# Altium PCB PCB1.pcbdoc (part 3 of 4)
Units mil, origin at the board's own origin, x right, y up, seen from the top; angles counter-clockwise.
Board outline 6180 x 7065 mil, 2 copper layers (Top Layer, Bottom Layer); 471 components, 245 nets, 1464 pads, 505 vias.
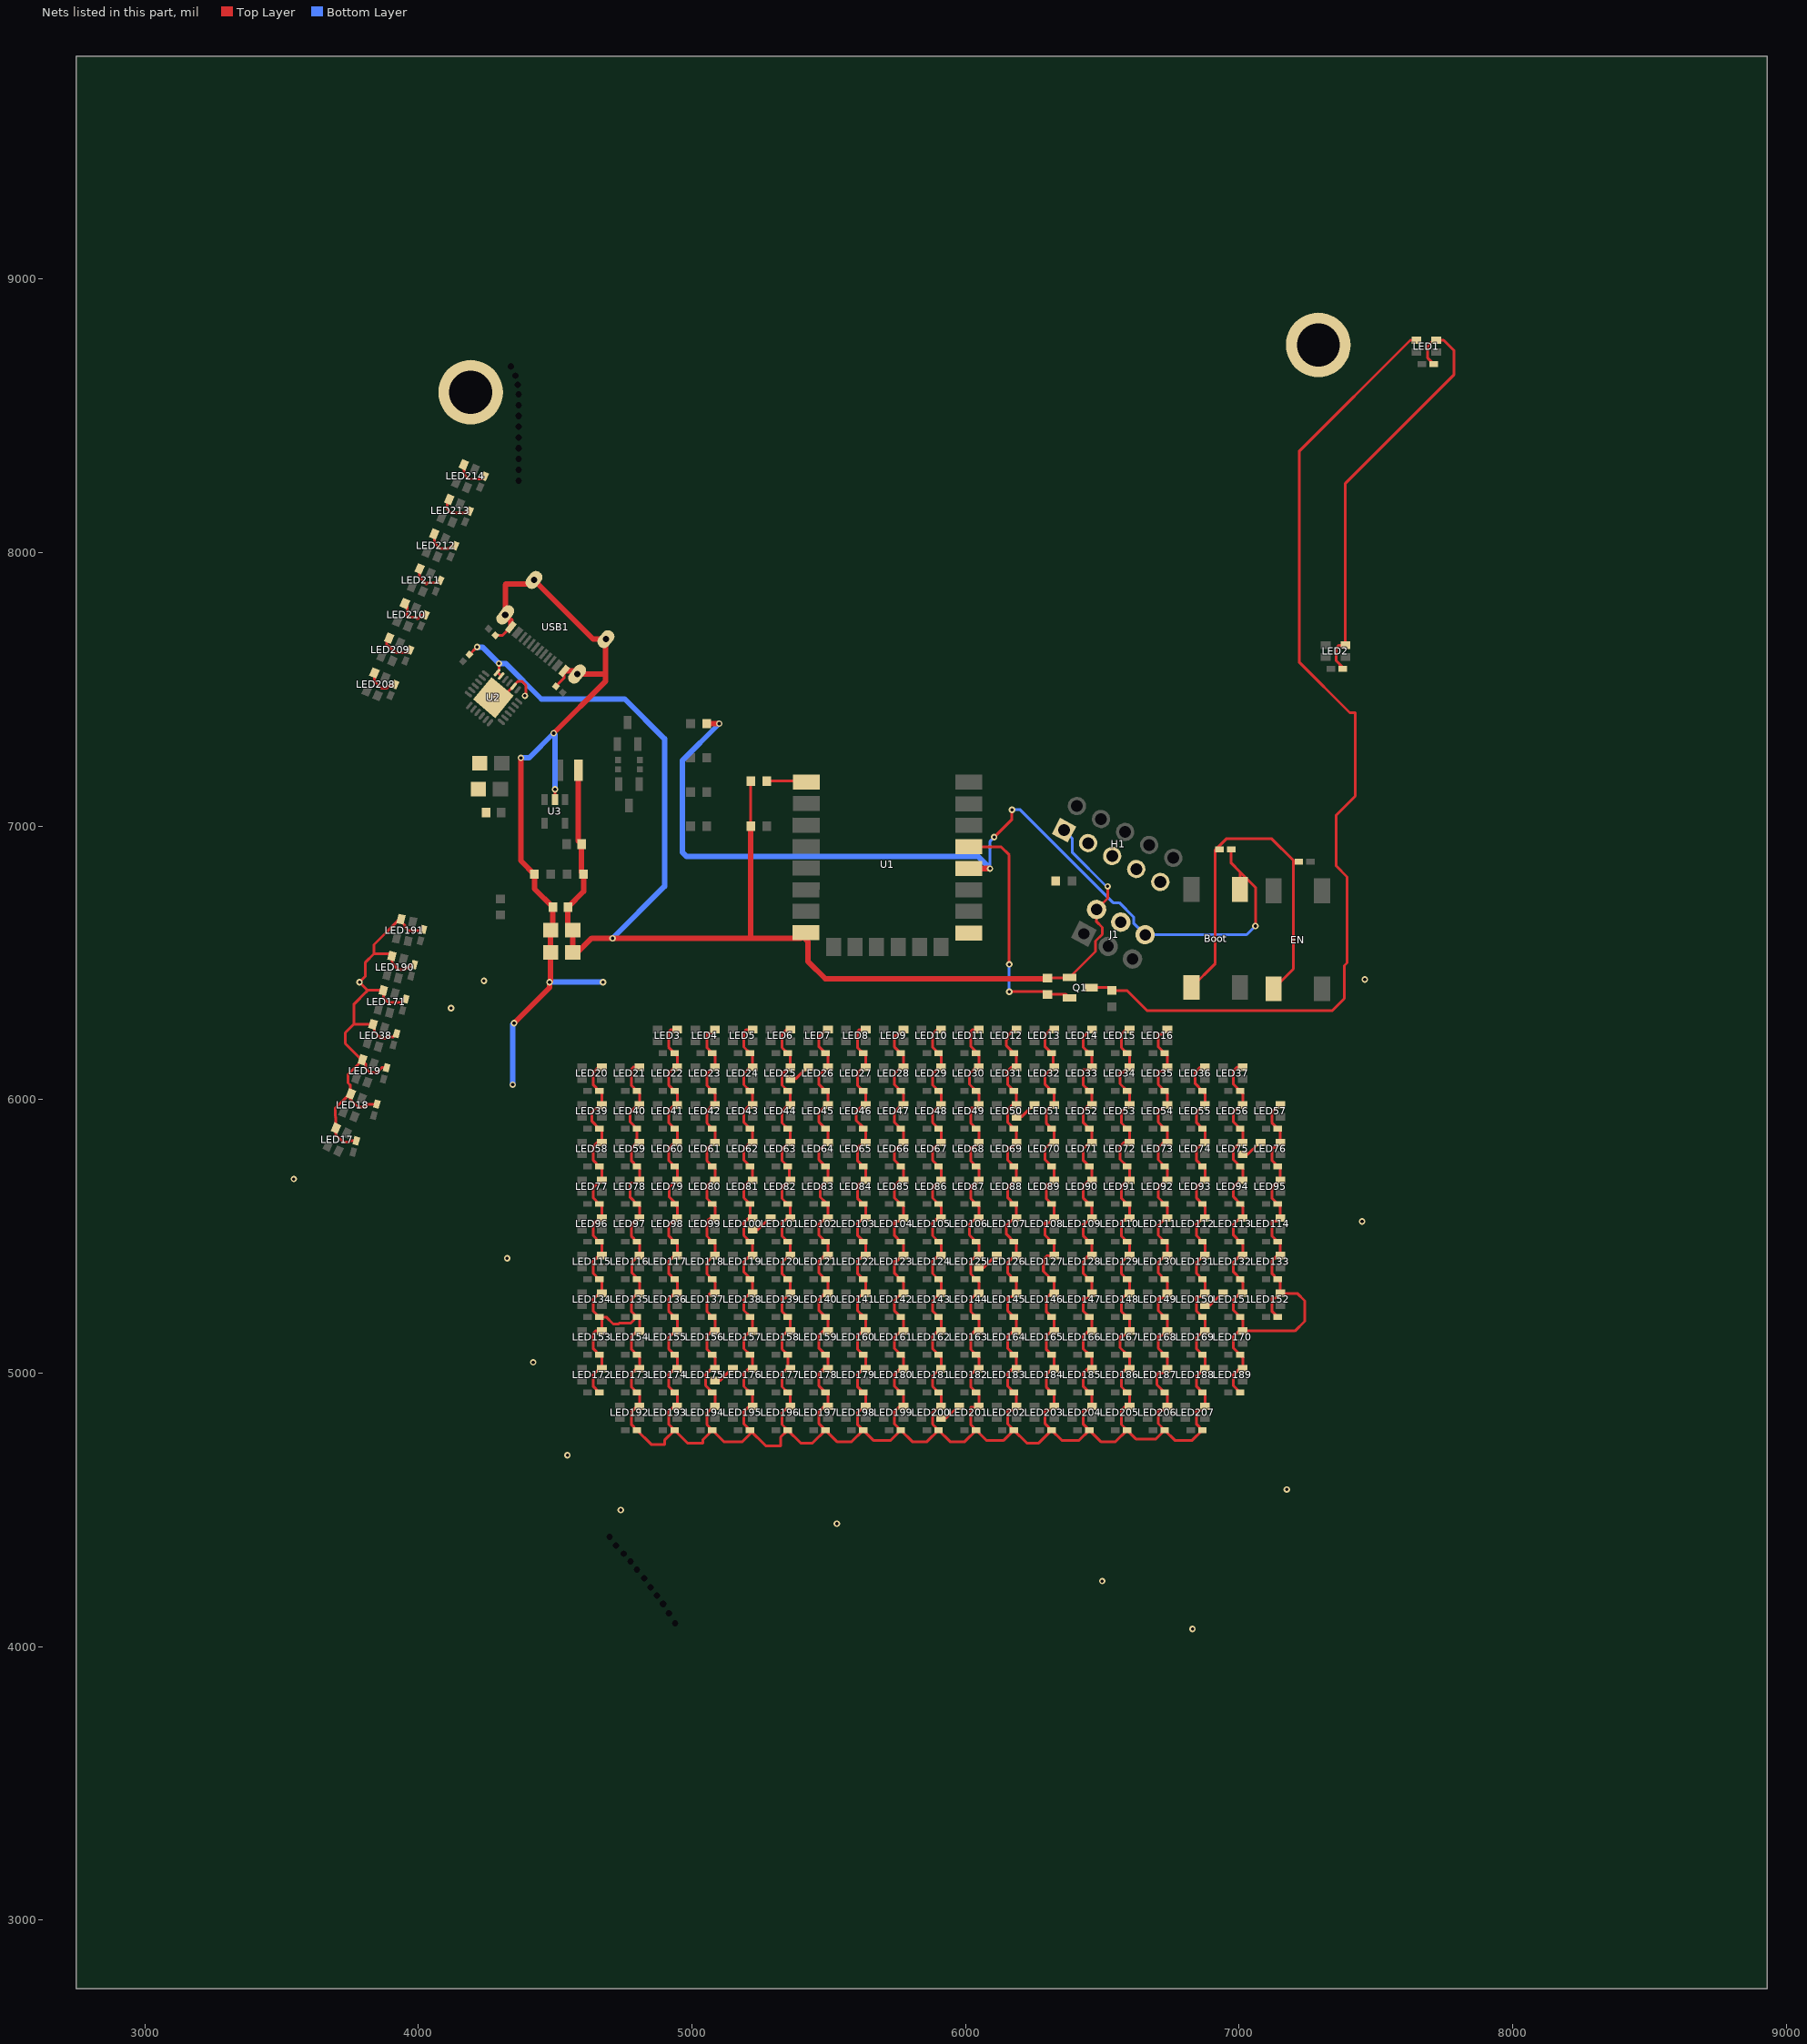
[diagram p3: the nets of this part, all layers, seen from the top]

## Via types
v1: diameter 24.02, hole 12.01, Top Layer to Bottom Layer, 504 vias
v2: diameter 23.62, hole 12.01, Top Layer to Bottom Layer, 1 vias

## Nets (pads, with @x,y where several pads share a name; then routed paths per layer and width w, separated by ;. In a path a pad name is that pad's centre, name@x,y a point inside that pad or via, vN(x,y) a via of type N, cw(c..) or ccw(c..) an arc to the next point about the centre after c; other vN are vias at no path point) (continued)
GND: Boot.1 C1.1 C2.1 C3.1 C4.1 C5.1 C6.1 C7.1 C8.1 C9.1 C10.1 C11.1 C12.1 C13.1 C14.1 C15.1 C16.1 C17.1 C18.1 C19.1 C20.1 C21.1 C22.1 C23.1 C24.1 C25.1 C26.1 C27.1 C28.1 C29.1 C30.1 C31.1 C32.1 C33.1 C34.1 C35.1 C36.1 C37.1 C38.1 C39.1 C40.1 C41.1 C42.1 C43.1 C44.1 C45.1 C46.1 C47.1 C48.1 C49.1 C50.1 C51.1 C52.1 C53.1 C54.1 C55.1 C56.1 C57.1 C58.1 C59.1 C60.1 C61.1 C62.1 C63.1 C64.1 C65.1 C66.1 C67.1 C68.1 C69.1 C70.1 C71.1 C72.1 C73.1 C74.1 C75.1 C76.1 C77.1 C78.1 C79.1 C80.1 C81.1 C82.1 C83.1 C84.1 C85.1 C86.1 C87.1 C88.1 C89.1 C90.1 C91.1 C92.1 C93.1 C94.1 C95.1 C96.1 C97.1 C98.1 C99.1 C100.1 C101.1 C102.1 C103.1 C104.1 C105.1 C106.1 C107.1 C108.1 C109.1 C110.1 C111.1 C112.1 C113.1 C114.1 C115.1 C116.1 C117.1 C118.1 C119.1 C120.1 C121.1 C122.1 C123.1 C124.1 C125.1 C126.1 C127.1 C128.1 C129.1 C130.1 C131.1 C132.1 C133.1 C134.1 C135.1 C136.1 C137.1 C138.1 C139.1 C140.1 C141.1 C142.1 C143.1 C144.1 C145.1 C146.1 C147.1 C148.1 C149.1 C150.1 C151.1 C152.1 C153.1 C154.1 C155.1 C156.1 C157.1 C158.1 C159.1 C160.1 C161.1 C162.1 C163.1 C164.1 C165.1 C166.1 C167.1 C168.1 C169.1 C170.1 C171.1 C172.1 C173.1 C174.1 C175.1 C176.1 C177.1 C178.1 C179.1 C180.1 C181.1 C182.1 C183.1 C184.1 C185.1 C186.1 C187.1 C188.1 C189.1 C190.1 C191.1 C192.1 C193.1 C194.1 C195.1 C196.1 C197.1 C198.1 C199.1 C200.1 C201.1 C202.1 C203.1 C204.1 C205.1 C206.1 C207.1 C208.1 C209.1 C210.1 C211.1 C212.1 C213.1 C214.1 C226.2 C227.2 C229.1 C230.1 C231.1 C233.1 C234.1 C235.1 EN.1 H1.3 H1.5 H1.7 H1.9 J1.4 LED1.2 LED2.2 LED3.2 LED4.2 LED5.2 LED6.2 LED7.2 LED8.2 LED9.2 LED10.2 LED11.2 LED12.2 LED13.2 LED14.2 LED15.2 LED16.2 LED17.2 LED18.2 LED19.2 LED20.2 LED21.2 LED22.2 LED23.2 LED24.2 LED25.2 LED26.2 LED27.2 LED28.2 LED29.2 LED30.2 LED31.2 LED32.2 LED33.2 LED34.2 LED35.2 LED36.2 LED37.2 LED38.2 LED39.2 LED40.2 LED41.2 LED42.2 LED43.2 LED44.2 LED45.2 LED46.2 LED47.2 LED48.2 LED49.2 LED50.2 LED51.2 LED52.2 LED53.2 LED54.2 LED55.2 LED56.2 LED57.2 LED58.2 LED59.2 LED60.2 LED61.2 LED62.2 LED63.2 LED64.2 LED65.2 LED66.2 LED67.2 LED68.2 LED69.2 LED70.2 LED71.2 LED72.2 LED73.2 LED74.2 LED75.2 LED76.2 LED77.2 LED78.2 LED79.2 LED80.2 LED81.2 LED82.2 LED83.2 LED84.2 LED85.2 LED86.2 LED87.2 LED88.2 LED89.2 LED90.2 LED91.2 LED92.2 LED93.2 LED94.2 LED95.2 LED96.2 LED97.2 LED98.2 LED99.2 LED100.2 LED101.2 LED102.2 LED103.2 LED104.2 LED105.2 LED106.2 LED107.2 LED108.2 LED109.2 LED110.2 LED111.2 LED112.2 LED113.2 LED114.2 LED115.2 LED116.2 LED117.2 LED118.2 LED119.2 LED120.2 LED121.2 LED122.2 LED123.2 LED124.2 LED125.2 LED126.2 LED127.2 LED128.2 LED129.2 LED130.2 LED131.2 LED132.2 LED133.2 LED134.2 LED135.2 LED136.2 LED137.2 LED138.2 LED139.2 LED140.2 LED141.2 LED142.2 LED143.2 LED144.2 LED145.2 LED146.2 LED147.2 LED148.2 LED149.2 LED150.2 LED151.2 LED152.2 LED153.2 LED154.2 LED155.2 LED156.2 LED157.2 LED158.2 LED159.2 LED160.2 LED161.2 LED162.2 LED163.2 LED164.2 LED165.2 LED166.2 LED167.2 LED168.2 LED169.2 LED170.2 LED171.2 LED172.2 LED173.2 LED174.2 LED175.2 LED176.2 LED177.2 LED178.2 LED179.2 LED180.2 LED181.2 LED182.2 LED183.2 LED184.2 LED185.2 LED186.2 LED187.2 LED188.2 LED189.2 LED190.2 LED191.2 LED192.2 LED193.2 LED194.2 LED195.2 LED196.2 LED197.2 LED198.2 LED199.2 LED200.2 LED201.2 LED202.2 LED203.2 LED204.2 LED205.2 LED206.2 LED207.2 LED208.2 LED209.2 LED210.2 LED211.2 LED212.2 LED213.2 LED214.2 pad.26 R3.1 R7.1 R8.1 R16.1 U1.9 U2.2 U2.25 U3.2 USB1.1 USB1.12 USB1.13 USB1.14 | length 45240
  Top Layer w10: LED18.2@3750.11,6016.53 3750.11,6002.83 3779.99,5972.95 3804.28,5972.95 3813.94,5982.61 C18.1@3846.22,5982.61 ; LED18.2@3755.23,6023.8 LED18.2@3751.93,6023.8 ; C17.1@3774.07,5849.89 3752.76,5849.89 3748.2,5845.33 3725.52,5845.33 3698.16,5872.7 3698.16,5937.08 3695.99,5939.24 3695.99,5967.86 LED18.2@3751.93,6023.8 ; LED19.2@3797.49,6146.83 LED19.2@3794.67,6144 ; 3810.95,6393.15 3810.95,6395.31 ; LED38.2@3834.37,6275.78 3764.11,6275.78 ; LED38.2@3839.28,6273.52 3839.28,6247.84 3862.13,6225 3880,6225 3885,6230 3908.65,6230 C38.1@3920.51,6241.86 ; LED208.2@3839.71,7560.42 3839.71,7530.29 3865,7505 3885,7505 3895,7515 3913.01,7515 C208.1@3915.71,7517.7 ; LED171.2@3872.5,6399.21 3872.5,6373.53 3891.03,6355 3935,6355 3947.55,6367.55 C171.1@3953.73,6367.55 ; LED171.2@3875.56,6400.96 3816.61,6400.96 3810.95,6395.31 ; C19.1@3885.26,6117.22 3866.54,6117.22 3849.03,6099.7 3822.92,6099.7 3807.46,6115.17 3807.46,6131.21 LED19.2@3794.67,6144 ; LED209.2@3893.65,7687.22 3885,7678.57 3885,7660 3890,7660 3915,7635 3960.15,7635 C209.1@3969.64,7644.5 ; LED190.2@3901.41,6527.49 3895.48,6533.41 3837.87,6533.41 ; LED190.2@3904.01,6525.35 3904.01,6499.67 3928.68,6475 3950,6475 3955,6480 3960,6480 3973.69,6493.69 C190.1@3985.24,6493.69 ; LED191.2@3930.21,6658.32 3950.94,6637.6 3950.94,6631.42 3963.8,6618.56 4016.98,6618.56 C191.1@4018.78,6620.37 ; LED191.2@3933.44,6662.63 3837.87,6567.06 3837.87,6533.41 ; LED210.2@3950.89,7814.66 3960,7805.56 3960,7765 3990,7765 3995,7760 4000,7760 4006.51,7766.51 4006.51,7771.51 4006.94,7771.94 C210.1@4026.89,7771.94 ; LED211.2@4004.83,7941.46 4004.83,7910.17 4030,7885 4035,7890 4072.09,7890 C211.1@4080.83,7898.74 ; LED212.2@4058.77,8068.26 4058.77,8036.23 4080,8015 4110,8015 4120.54,8025.54 C212.1@4134.76,8025.54 ; LED213.2@4112.7,8195.06 4105,8187.36 4105,8160 4120,8145 4181.36,8145 C213.1@4188.7,8152.34 ; LED214.2@4166.64,8321.86 4166.64,8288.36 4185,8270 4233.49,8270 C214.1@4242.64,8279.14 ; U2.25@4281.89,7468.8 4305.53,7468.8 U2.2@4347.16,7510.43 ; R8.1@4282.35,7698.26 4308.7,7698.26 USB1.12@4338.3,7727.87 ; U2.2@4354.15,7519.47 4365.18,7530.51 4378.26,7530.51 4393.56,7515.2 4393.56,7480.57 v2(4389.85,7476.85) ; U3.2@4499.29,7097.6 4500,7098.31 v1(4500,7135) ; R7.1@4502.47,7511.54 4532.85,7541.93 USB1.1@4532.85,7567.74 ; C172.1@4661.46,4929.84 4640,4951.3 4640,4995.47 4661.02,5016.5 LED172.2@4671.02,5016.5 4671.02,5058.07 C153.1@4661.46,5067.64 4640,5089.1 4640,5145.98 4648.31,5154.29 LED153.2@4671.02,5154.29 4671.02,5195.87 C134.1@4661.46,5205.43 ; LED20.2@4671.02,6118.86 4658.86,6118.86 4640,6100 4640,6053.66 C20.1@4661.46,6032.2 4671.02,6022.64 LED39.2@4671.02,5981.06 4659.63,5969.67 4649.67,5969.67 4635,5955 4635,5920.87 C39.1@4661.46,5894.41 4671.02,5884.84 LED58.2@4671.02,5843.27 4653.27,5843.27 4640,5830 4640,5778.07 C58.1@4661.46,5756.61 4671.02,5747.05 LED77.2@4671.02,5705.47 4665.47,5705.47 4640,5680 4640,5640.28 C77.1@4661.46,5618.82 4671.02,5609.25 LED96.2@4671.02,5567.68 4661.02,5567.68 4640,5546.65 4640,5502.48 C96.1@4661.46,5481.02 4671.02,5471.46 LED115.2@4671.02,5429.88 4659.88,5429.88 4640,5410 4640,5364.69 C115.1@4661.46,5343.23 4671.02,5333.66 LED134.2@4671.02,5292.09 4661.02,5292.09 4640,5271.06 4640,5226.89 C134.1@4661.46,5205.43 ; LED21.2@4808.82,6118.86 4786.1,6118.86 4780,6112.76 4780,6051.46 C21.1@4799.26,6032.2 4808.82,6022.64 LED40.2@4808.82,5981.06 4801.06,5981.06 4775,5955 4775,5918.66 C40.1@4799.26,5894.41 4799.26,5852.83 LED59.2@4808.82,5843.27 4798.27,5843.27 4780,5825 4780,5775.87 C59.1@4799.26,5756.61 4808.82,5747.05 LED78.2@4808.82,5705.47 4798.35,5695 4775,5695 4775,5643.07 C78.1@4799.26,5618.82 4808.82,5609.25 LED97.2@4808.82,5567.68 4802.68,5567.68 4780,5545 4780,5500.28 C97.1@4799.26,5481.02 4808.82,5471.46 LED116.2@4808.82,5429.88 4805.1,5429.88 4780.12,5404.9 4780.12,5368.24 4799.26,5349.11 C116.1@4799.26,5343.23 4808.82,5333.66 LED135.2@4808.82,5292.09 4802.09,5292.09 4780,5270 4780,5224.69 C135.1@4799.26,5205.43 ; LED3.2@4946.62,6256.65 4923.9,6256.65 4915,6247.76 4915,6192.05 C3.1@4937.05,6170 4946.62,6160.44 LED22.2@4946.62,6118.86 4936.62,6118.86 4915,6097.24 4915,6054.26 C22.1@4937.05,6032.2 4946.62,6022.64 LED41.2@4946.62,5981.06 4936.62,5981.06 4915,5959.45 4915,5916.46 C41.1@4937.05,5894.41 4946.62,5884.84 LED60.2@4946.62,5843.27 4936.62,5843.27 4915,5821.65 4915,5778.66 C60.1@4937.05,5756.61 4946.62,5747.05 LED79.2@4946.62,5705.47 4942.9,5705.47 4917.91,5680.49 4917.91,5643.83 4937.05,5624.7 C79.1@4937.05,5618.82 4946.62,5609.25 LED98.2@4946.62,5567.68 4942.68,5567.68 4915,5540 4915,5503.07 C98.1@4937.05,5481.02 4946.62,5471.46 LED117.2@4946.62,5429.88 4936.62,5429.88 4915,5408.27 4915,5365.28 C117.1@4937.05,5343.23 4946.62,5333.66 LED136.2@4946.62,5292.09 4936.62,5292.09 4915,5270.47 4915,5227.48 C136.1@4937.05,5205.43 4946.62,5195.87 LED155.2@4946.62,5154.29 4939.29,5154.29 4915,5130 4915,5089.69 C155.1@4937.05,5067.64 4946.62,5058.07 LED174.2@4946.62,5016.5 4936.62,5016.5 4915,4994.88 4915,4951.89 C174.1@4937.05,4929.84 4946.62,4920.28 LED193.2@4946.62,4878.7 4933.7,4878.7 4915,4860 4915,4814.1 C193.1@4937.05,4792.05 ; LED4.2@5084.41,6256.65 5072.76,6245 5055,6245 5056.72,6243.28 5056.72,6231.72 5055,6230 5055,6189.85 C4.1@5074.85,6170 5084.41,6160.44 LED23.2@5084.41,6118.86 5080.47,6118.86 5061.61,6100 5055,6100 5055,6052.05 C23.1@5074.85,6032.2 5084.41,6022.64 LED42.2@5084.41,5981.06 5076.06,5981.06 5055,5960 5055,5914.26 C42.1@5074.85,5894.41 5084.41,5884.84 LED61.2@5084.41,5843.27 5078.27,5843.27 5055,5820 5055,5776.46 C61.1@5074.85,5756.61 5084.41,5747.05 LED80.2@5084.41,5705.47 5075.47,5705.47 5055,5685 5055,5638.66 C80.1@5074.85,5618.82 5084.41,5609.25 LED99.2@5084.41,5567.68 5067.68,5567.68 5058.11,5558.11 5058.11,5545 5055,5545 5055,5500.87 C99.1@5074.85,5481.02 5084.41,5471.46 LED118.2@5084.41,5429.88 5079.88,5429.88 5055,5405 5055,5363.07 C118.1@5074.85,5343.23 5084.41,5333.66 LED137.2@5084.41,5292.09 5067.09,5292.09 5055,5280 5056.41,5278.59 5056.41,5266.41 5055,5265 5055,5225.28 C137.1@5074.85,5205.43 5084.41,5195.87 LED156.2@5084.41,5154.29 5074.29,5154.29 5055,5135 5055,5087.48 C156.1@5074.85,5067.64 5084.41,5058.07 LED175.2@5084.41,5016.5 5071.5,5016.5 5050,4995 5050,4954.69 C175.1@5074.85,4929.84 5084.41,4920.28 LED194.2@5084.41,4878.7 5078.7,4878.7 5055,4855 5055,4811.89 C194.1@5074.85,4792.05 ; LED5.2@5222.21,6256.65 5199.49,6256.65 5190,6247.17 5190,6192.64 C5.1@5212.64,6170 5222.21,6160.44 LED24.2@5222.21,6118.86 5212.21,6118.86 5190,6096.65 5190,6054.85 C24.1@5212.64,6032.2 5222.21,6022.64 LED43.2@5222.21,5981.06 5212.21,5981.06 5190,5958.86 5190,5917.05 C43.1@5212.64,5894.41 5222.21,5884.84 LED62.2@5222.21,5843.27 5212.21,5843.27 5190,5821.06 5190,5779.26 C62.1@5212.64,5756.61 5222.21,5747.05 LED81.2@5222.21,5705.47 5212.21,5705.47 5190,5683.27 5190,5641.46 C81.1@5212.64,5618.82 5212.64,5577.24 LED100.2@5222.21,5567.68 5207.42,5567.68 5190,5550.26 5190,5503.66 C100.1@5212.64,5481.02 5222.21,5471.46 LED119.2@5222.21,5429.88 5212.21,5429.88 5190,5407.68 5190,5370 5212.64,5347.36 C119.1@5212.64,5343.23 5222.21,5333.66 LED138.2@5222.21,5292.09 5212.21,5292.09 5190,5269.88 5190,5230 5212.64,5207.36 C138.1@5212.64,5205.43 5222.21,5195.87 LED157.2@5222.21,5154.29 5214.29,5154.29 5190,5130 5190,5090.28 C157.1@5212.64,5067.64 5222.21,5058.07 LED176.2@5222.21,5016.5 5206.5,5016.5 5190,5000 5190,4952.48 C176.1@5212.64,4929.84 5222.21,4920.28 LED195.2@5222.21,4878.7 5208.7,4878.7 5190,4860 5190,4814.69 C195.1@5212.64,4792.05 ; LED82.2@5360,5705.47 LED82.2@5356.06,5705.47 ; LED6.2@5360,6256.65 5346.65,6256.65 5330,6240 5330,6190.44 C6.1@5350.44,6170 5360,6160.44 LED25.2@5360,6118.86 5356.06,6118.86 5337.2,6100 5330,6100 5330,6052.64 C25.1@5350.44,6032.2 5360,6022.64 LED44.2@5360,5981.06 5351.06,5981.06 5330,5960 5330,5914.85 C44.1@5350.44,5894.41 5360,5884.84 LED63.2@5360,5843.27 5353.27,5843.27 5330,5820 5330,5777.05 C63.1@5350.44,5756.61 5356.06,5750.99 LED82.2@5356.06,5705.47 ; LED7.2@5497.8,6256.65 5491.65,6256.65 5465,6230 5465,6193.23 C7.1@5488.23,6170 5497.8,6160.44 LED26.2@5497.8,6118.86 5493.86,6118.86 5465,6090 5465,6055.44 C26.1@5488.23,6032.2 5497.8,6022.64 LED45.2@5497.8,5981.06 5491.06,5981.06 5465,5955 5465,5917.64 C45.1@5488.23,5894.41 5497.8,5884.84 LED64.2@5497.8,5843.27 5493.27,5843.27 5465,5815 5465,5779.85 C64.1@5488.23,5756.61 5497.8,5747.05 LED83.2@5497.8,5705.47 5494.08,5705.47 5469.1,5680.49 5469.1,5643.83 5488.23,5624.7 C83.1@5488.23,5618.82 5497.8,5609.25 LED102.2@5497.8,5567.68 5487.68,5567.68 5465,5545 5465,5504.26 C102.1@5488.23,5481.02 5497.8,5471.46 LED121.2@5497.8,5429.88 5484.88,5429.88 5465,5410 5465,5366.46 C121.1@5488.23,5343.23 5497.8,5333.66 LED140.2@5497.8,5292.09 5487.09,5292.09 5465,5270 5465,5228.66 C140.1@5488.23,5205.43 5497.8,5195.87 LED159.2@5497.8,5154.29 5479.29,5154.29 5465,5140 5465,5090.87 C159.1@5488.23,5067.64 5497.8,5058.07 LED178.2@5497.8,5016.5 5481.5,5016.5 5465,5000 5465,4953.07 C178.1@5488.23,4929.84 5497.8,4920.28 LED197.2@5497.8,4878.7 5483.7,4878.7 5465,4860 5465,4815.28 C197.1@5488.23,4792.05 ; LED8.2@5635.59,6256.65 5612.88,6256.65 5605,6248.78 5605,6191.03 C8.1@5626.03,6170 5635.59,6160.44 LED27.2@5635.59,6118.86 5625.59,6118.86 5605,6098.27 5605,6053.23 C27.1@5626.03,6032.2 5635.59,6022.64 LED46.2@5635.59,5981.06 5625.59,5981.06 5600,5955.47 5600,5925 5626.03,5898.97 C46.1@5626.03,5894.41 5635.59,5884.84 LED65.2@5635.59,5843.27 5625.59,5843.27 5605,5822.68 5605,5777.64 C65.1@5626.03,5756.61 5635.59,5747.05 LED84.2@5635.59,5705.47 5625.59,5705.47 5605,5684.88 5605,5639.85 C84.1@5626.03,5618.82 5635.59,5609.25 LED103.2@5635.59,5567.68 5625.59,5567.68 5605,5547.09 5605,5505 5626.03,5483.97 C103.1@5626.03,5481.02 5635.59,5471.46 LED122.2@5635.59,5429.88 5625.59,5429.88 5605,5409.29 5605,5365 5626.03,5343.97 C122.1@5626.03,5343.23 5635.59,5333.66 LED141.2@5635.59,5292.09 5625.59,5292.09 5605,5271.5 5605,5230 5626.03,5208.97 C141.1@5626.03,5205.43 5635.59,5195.87 LED160.2@5635.59,5154.29 5624.29,5154.29 5605,5135 5605,5088.66 C160.1@5626.03,5067.64 5635.59,5058.07 LED179.2@5635.59,5016.5 5626.5,5016.5 5605,4995 5605,4950.87 C179.1@5626.03,4929.84 5635.59,4920.28 LED198.2@5635.59,4878.7 5628.7,4878.7 5605,4855 5605,4813.07 C198.1@5626.03,4792.05 ; LED9.2@5773.39,6256.65 5769.45,6256.65 5747.8,6235 5740,6235 5740,6193.82 C9.1@5763.82,6170 5773.39,6160.44 LED28.2@5773.39,6118.86 5763.86,6118.86 5740,6095 5740,6056.03 C28.1@5763.82,6032.2 5773.39,6022.64 LED47.2@5773.39,5981.06 5766.06,5981.06 5740,5955 5740,5918.23 C47.1@5763.82,5894.41 5773.39,5884.84 LED66.2@5773.39,5843.27 5768.27,5843.27 5740,5815 5740,5780.44 C66.1@5763.82,5756.61 5773.39,5747.05 LED85.2@5773.39,5705.47 5760.47,5705.47 5740,5685 5740,5642.64 C85.1@5763.82,5618.82 5773.39,5609.25 LED104.2@5773.39,5567.68 5760.71,5555 5740,5555 5740,5504.85 C104.1@5763.82,5481.02 5773.39,5471.46 LED123.2@5773.39,5429.88 5769.45,5429.88 5749.57,5410 5740,5410 5740,5367.05 C123.1@5763.82,5343.23 5773.39,5333.66 LED142.2@5773.39,5292.09 5767.09,5292.09 5740,5265 5740,5229.26 C142.1@5763.82,5205.43 5773.39,5195.87 LED161.2@5773.39,5154.29 5764.29,5154.29 5740,5130 5740,5091.46 C161.1@5763.82,5067.64 5773.39,5058.07 LED180.2@5773.39,5016.5 5761.5,5016.5 5740,4995 5740,4953.66 C180.1@5763.82,4929.84 5773.39,4920.28 LED199.2@5773.39,4878.7 5758.7,4878.7 5740,4860 5740,4815.87 C199.1@5763.82,4792.05 ; 5884.16,4855 5880,4855 ; LED10.2@5911.18,6256.65 5896.65,6256.65 5880,6240 5880,6191.62 C10.1@5901.62,6170 5911.18,6160.44 LED29.2@5911.18,6118.86 5903.86,6118.86 5880,6095 5880,6053.82 C29.1@5901.62,6032.2 5911.18,6022.64 LED48.2@5911.18,5981.06 5906.06,5981.06 5880,5955 5880,5916.03 C48.1@5901.62,5894.41 5911.18,5884.84 LED67.2@5911.18,5843.27 5903.27,5843.27 5880,5820 5880,5778.23 C67.1@5901.62,5756.61 5911.18,5747.05 LED86.2@5911.18,5705.47 5905.47,5705.47 5880,5680 5880,5640.44 C86.1@5901.62,5618.82 5911.18,5609.25 LED105.2@5911.18,5567.68 5897.68,5567.68 5880,5550 5880,5502.64 C105.1@5901.62,5481.02 5911.18,5471.46 LED124.2@5911.18,5429.88 5899.88,5429.88 5880,5410 5880,5364.85 C124.1@5901.62,5343.23 5911.18,5333.66 LED143.2@5911.18,5292.09 5907.09,5292.09 5880,5265 5880,5227.05 C143.1@5901.62,5205.43 5911.18,5195.87 LED162.2@5911.18,5154.29 5899.29,5154.29 5880,5135 5880,5089.26 C162.1@5901.62,5067.64 5911.18,5058.07 LED181.2@5911.18,5016.5 5906.5,5016.5 5880,4990 5880,4951.46 C181.1@5901.62,4929.84 5911.18,4920.28 LED200.2@5911.18,4878.7 5903.7,4878.7 5880,4855 ; LED11.2@6048.98,6256.65 6026.26,6256.65 6020,6250.39 6020,6195 6039.41,6175.59 C11.1@6039.41,6170 6048.98,6160.44 LED30.2@6048.98,6118.86 6038.98,6118.86 6015,6094.88 6015,6056.62 C30.1@6039.41,6032.2 6048.98,6022.64 LED49.2@6048.98,5981.06 6037.91,5970 6020,5970 6021.43,5968.57 6021.43,5956.43 6020,5955 6020,5913.82 C49.1@6039.41,5894.41 6048.98,5884.84 LED68.2@6048.98,5843.27 6030.71,5825 6020,5825 6020,5776.03 C68.1@6039.41,5756.61 6048.98,5747.05 LED87.2@6048.98,5705.47 6045.04,5705.47 6024.57,5685 6020,5685 6020,5638.23 C87.1@6039.41,5618.82 6048.98,5609.25 LED106.2@6048.98,5567.68 6037.68,5567.68 6015,5545 6015,5505.44 C106.1@6039.41,5481.02 6048.98,5471.46 LED125.2@6048.98,5429.88 6039.88,5429.88 6020,5410 6020,5362.64 C125.1@6039.41,5343.23 6048.98,5333.66 LED144.2@6048.98,5292.09 6042.09,5292.09 6020,5270 6020,5224.85 C144.1@6039.41,5205.43 6048.98,5195.87 LED163.2@6048.98,5154.29 6034.29,5154.29 6020,5140 6020,5087.05 C163.1@6039.41,5067.64 6048.98,5058.07 LED182.2@6048.98,5016.5 6041.5,5016.5 6020,4995 6020,4949.26 C182.1@6039.41,4929.84 6048.98,4920.28 LED201.2@6048.98,4878.7 6045.28,4875 6020,4875 6020,4811.46 C201.1@6039.41,4792.05 ; LED12.2@6186.77,6256.65 6176.65,6256.65 6155,6235 6155,6225 6150,6220 6150,6197.21 C12.1@6177.21,6170 6186.77,6160.44 LED31.2@6186.77,6118.86 6168.86,6118.86 6150,6100 6155,6095 6155,6054.41 C31.1@6177.21,6032.2 6186.77,6022.64 LED50.2@6186.77,5981.06 6171.06,5981.06 6155,5965 6155,5916.62 C50.1@6177.21,5894.41 6186.77,5884.84 LED69.2@6186.77,5843.27 6168.5,5825 6155,5825 6155,5778.82 C69.1@6177.21,5756.61 6186.77,5747.05 LED88.2@6186.77,5705.47 6180.47,5705.47 6155,5680 6155,5641.03 C88.1@6177.21,5618.82 6186.77,5609.25 LED107.2@6186.77,5567.68 6177.68,5567.68 6150,5540 6150,5508.23 C107.1@6177.21,5481.02 6186.77,5471.46 LED126.2@6186.77,5429.88 6179.88,5429.88 6155,5405 6155,5365.44 C126.1@6177.21,5343.23 6186.77,5333.66 LED145.2@6186.77,5292.09 6174.68,5280 6155,5280 6155,5227.64 C145.1@6177.21,5205.43 6186.77,5195.87 LED164.2@6186.77,5154.29 6174.29,5154.29 6155,5135 6155,5089.85 C164.1@6177.21,5067.64 6186.77,5058.07 LED183.2@6186.77,5016.5 6171.5,5016.5 6155,5000 6155,4952.05 C183.1@6177.21,4929.84 6186.77,4920.28 LED202.2@6186.77,4878.7 6173.07,4865 6155,4865 6155,4814.26 C202.1@6177.21,4792.05 ; LED32.2@6324.57,6118.86 LED32.2@6320.63,6118.86 ; LED13.2@6324.57,6256.65 6311.65,6256.65 6290,6235 6290,6195 C13.1@6315,6170 6320.63,6164.37 LED32.2@6320.63,6118.86 ; LED14.2@6462.36,6256.65 6458.43,6256.65 6436.77,6235 6430,6235 6430,6192.8 C14.1@6452.8,6170 6462.36,6160.44 LED33.2@6462.36,6118.86 6453.5,6110 6430,6110 6430,6055 C33.1@6452.8,6032.2 6462.36,6022.64 LED52.2@6462.36,5981.06 6451.06,5981.06 6430,5960 6430,5917.21 C52.1@6452.8,5894.41 6462.36,5884.84 LED71.2@6462.36,5843.27 6453.27,5843.27 6430,5820 6430,5779.41 C71.1@6452.8,5756.61 6462.36,5747.05 LED90.2@6462.36,5705.47 6450.47,5705.47 6430,5685 6430,5641.62 C90.1@6452.8,5618.82 6462.36,5609.25 LED109.2@6462.36,5567.68 6458.43,5567.68 6435.75,5545 6430,5545 6430,5503.82 C109.1@6452.8,5481.02 6462.36,5471.46 LED128.2@6462.36,5429.88 6449.88,5429.88 6435,5415 6435,5410 6430,5405 6430,5366.03 C128.1@6452.8,5343.23 6462.36,5333.66 LED147.2@6462.36,5292.09 6445.28,5275 6430,5275 6430,5228.23 C147.1@6452.8,5205.43 6462.36,5195.87 LED166.2@6462.36,5154.29 6449.29,5154.29 6430,5135 6430,5090.44 C166.1@6452.8,5067.64 6462.36,5058.07 LED185.2@6462.36,5016.5 6446.5,5016.5 6430,5000 6430,4952.64 C185.1@6452.8,4929.84 6462.36,4920.28 LED204.2@6462.36,4878.7 6448.66,4865 6430,4865 6430,4814.85 C204.1@6452.8,4792.05 ; LED15.2@6600.16,6256.65 6586.65,6256.65 6570,6240 6570,6190.59 C15.1@6590.59,6170 6600.16,6160.44 LED34.2@6600.16,6118.86 6596.22,6118.86 6577.36,6100 6565,6100 6565,6057.8 C34.1@6590.59,6032.2 6600.16,6022.64 LED53.2@6600.16,5981.06 6596.22,5981.06 6575.16,5960 6570,5960 6570,5915 C53.1@6590.59,5894.41 6600.16,5884.84 LED72.2@6600.16,5843.27 6578.27,5843.27 6565,5830 6565,5782.21 C72.1@6590.59,5756.61 6600.16,5747.05 LED91.2@6600.16,5705.47 6590.47,5705.47 6570,5685 6570,5639.41 C91.1@6590.59,5618.82 6600.16,5609.25 LED110.2@6600.16,5567.68 6587.68,5567.68 6570,5550 6570,5501.62 C110.1@6590.59,5481.02 6600.16,5471.46 LED129.2@6600.16,5429.88 6594.88,5429.88 6570,5405 6570,5363.82 C129.1@6590.59,5343.23 6600.16,5333.66 LED148.2@6600.16,5292.09 6592.09,5292.09 6570,5270 6570,5226.03 C148.1@6590.59,5205.43 6600.16,5195.87 LED167.2@6600.16,5154.29 6596.22,5154.29 6576.93,5135 6565,5135 6565,5093.23 C167.1@6590.59,5067.64 6600.16,5058.07 LED186.2@6600.16,5016.5 6586.5,5016.5 6570,5000 6570,4950.44 C186.1@6590.59,4929.84 6600.16,4920.28 LED205.2@6600.16,4878.7 6583.7,4878.7 6570,4865 6570,4812.64 C205.1@6590.59,4792.05 ; LED16.2@6737.95,6256.65 6721.3,6240 6705,6240 6705,6193.39 C16.1@6728.39,6170 6737.95,6160.44 LED35.2@6737.95,6118.86 6724.09,6105 6705,6105 6705,6055.59 C35.1@6728.39,6032.2 6737.95,6022.64 LED54.2@6737.95,5981.06 6721.89,5965 6705,5965 6705,5917.8 C54.1@6728.39,5894.41 6737.95,5884.84 LED73.2@6737.95,5843.27 6723.27,5843.27 6705,5825 6705,5780 C73.1@6728.39,5756.61 6737.95,5747.05 LED92.2@6737.95,5705.47 6730.47,5705.47 6705,5680 6705,5642.21 C92.1@6728.39,5618.82 6737.95,5609.25 LED111.2@6737.95,5567.68 6732.68,5567.68 6705,5540 6705,5504.41 C111.1@6728.39,5481.02 6737.95,5471.46 LED130.2@6737.95,5429.88 6729.88,5429.88 6705,5405 6705,5366.62 C130.1@6728.39,5343.23 6737.95,5333.66 LED149.2@6737.95,5292.09 6720.87,5275 6705,5275 6705,5228.82 C149.1@6728.39,5205.43 6737.95,5195.87 LED168.2@6737.95,5154.29 6734.02,5154.29 6714.72,5135 6705,5135 6705,5091.03 C168.1@6728.39,5067.64 6737.95,5058.07 LED187.2@6737.95,5016.5 6721.46,5000 6700,5000 6700,4958.23 C187.1@6728.39,4929.84 6737.95,4920.28 LED206.2@6737.95,4878.7 6724.25,4865 6705,4865 6705,4815.44 C206.1@6728.39,4792.05 ; Boot.1@6826.41,6410.87 6913.54,6497.99 6913.54,6913.54 6955,6955 7118.54,6955 7198.54,6875 7198.54,6477.99 EN.1@7126.41,6405.87 ; LED36.2@6875.75,6118.86 6858.86,6118.86 6840,6100 6840,6058.39 C36.1@6866.18,6032.2 6875.75,6022.64 LED55.2@6875.75,5981.06 6871.06,5981.06 6845,5955 6845,5915.59 C55.1@6866.18,5894.41 6875.75,5884.84 LED74.2@6875.75,5843.27 6868.27,5843.27 6845,5820 6845,5777.8 C74.1@6866.18,5756.61 6875.75,5747.05 LED93.2@6875.75,5705.47 6870.47,5705.47 6845,5680 6845,5640 C93.1@6866.18,5618.82 6875.75,5609.25 LED112.2@6875.75,5567.68 6867.68,5567.68 6845,5545 6845,5502.21 C112.1@6866.18,5481.02 6875.75,5471.46 LED131.2@6875.75,5429.88 6869.88,5429.88 6845,5405 6845,5364.41 C131.1@6866.18,5343.23 6875.75,5333.66 LED150.2@6875.75,5292.09 6863.66,5280 6845,5280 6845,5226.62 C150.1@6866.18,5205.43 6875.75,5195.87 LED169.2@6875.75,5154.29 6869.29,5154.29 6845,5130 6845,5088.82 C169.1@6866.18,5067.64 6875.75,5058.07 LED188.2@6875.75,5016.5 6871.5,5016.5 6845,4990 6845,4951.03 C188.1@6866.18,4929.84 6875.75,4920.28 LED207.2@6875.75,4878.7 6862.05,4865 6845,4865 6845,4813.23 C207.1@6866.18,4792.05 6829.14,4755 6765.44,4755 C206.1@6728.39,4792.05 ; C189.1@7003.98,4929.84 6980,4953.82 6980,4995 7001.5,5016.5 LED189.2@7013.54,5016.5 7013.54,5058.07 C170.1@7003.98,5067.64 6980,5091.62 6980,5135 6999.29,5154.29 LED170.2@7013.54,5154.29 ; LED37.2@7013.54,6118.86 6993.86,6118.86 6980,6105 6980,6056.18 C37.1@7003.98,6032.2 7013.54,6022.64 LED56.2@7013.54,5981.06 7006.06,5981.06 6980,5955 6980,5918.39 C56.1@7003.98,5894.41 7013.54,5884.84 LED75.2@7013.54,5843.27 7003.54,5843.27 6980,5819.72 6980,5780.59 C75.1@7003.98,5756.61 7013.54,5747.05 LED94.2@7013.54,5705.47 7003.54,5705.47 6980,5681.93 6980,5645 7003.98,5621.02 C94.1@7003.98,5618.82 7013.54,5609.25 LED113.2@7013.54,5567.68 7003.54,5567.68 6980,5544.13 6980,5505 C113.1@7003.98,5481.02 7013.54,5471.46 LED132.2@7013.54,5429.88 7003.54,5429.88 6980,5406.34 6980,5370 7003.98,5346.02 C132.1@7003.98,5343.23 7013.54,5333.66 LED151.2@7013.54,5292.09 7003.54,5292.09 6980,5268.54 6980,5230 7003.98,5206.02 C151.1@7003.98,5205.43 7013.54,5195.87 LED170.2@7013.54,5154.29 ; C152.1@7141.77,5205.43 7120,5227.21 7120,5275 7134.25,5275 LED152.2@7151.34,5292.09 ; LED57.2@7151.34,5981.06 7147.4,5981.06 7126.34,5960 7120,5960 7120,5916.18 C57.1@7141.77,5894.41 7151.34,5884.84 LED76.2@7151.34,5843.27 7133.07,5825 7120,5825 7120,5778.39 C76.1@7141.77,5756.61 7151.34,5747.05 LED95.2@7151.34,5705.47 7145.47,5705.47 7120,5680 7120,5640.59 C95.1@7141.77,5618.82 7151.34,5609.25 LED114.2@7151.34,5567.68 7138.66,5555 7120,5555 7120,5502.8 C114.1@7141.77,5481.02 7151.34,5471.46 LED133.2@7151.34,5429.88 7139.88,5429.88 7120,5410 7120,5365 C133.1@7141.77,5343.23 7151.34,5333.66 LED152.2@7151.34,5292.09 ; C2.1@7379.26,7575 7379.26,7580.74 7355,7605 7355,7650.55 7366.1,7661.65 LED2.2@7388.82,7661.65 7388.82,8253.82 7785,8650 7785,8740 7748.35,8776.66 LED1.2@7721.02,8776.66 7711.65,8776.66 7690,8755 7690,8711.46 C1.1@7711.46,8690 ; LED18.2@3751.93,6023.8 3751.93,6052.29 3742.93,6061.28 3742.93,6092.26 LED19.2@3794.67,6144 ; 3764.11,6275.78 3733.15,6244.82 3733.15,6205.52 LED19.2@3794.67,6144 ; 3764.11,6275.78 3764.11,6348.47 3810.95,6395.31 ; 3810.95,6395.31 3810.95,6404.05 v1(3785,6430) 3807.01,6452.01 3807.01,6502.54 3837.87,6533.41 ; C134.1@4661.46,5205.43 4687.24,5205.43 4713.03,5179.65 4732.08,5179.65 4736.25,5183.82 4777.64,5183.82 C135.1@4799.26,5205.43 ; C135.1@4799.26,5205.43 4808.82,5195.87 LED154.2@4808.82,5154.29 4799.29,5154.29 4780,5135 4780,5086.89 C154.1@4799.26,5067.64 4808.82,5058.07 LED173.2@4808.82,5016.5 4796.5,5016.5 4780,5000 4780.82,4999.18 4780.82,4990.82 4780,4990 4780,4949.1 C173.1@4799.26,4929.84 4808.82,4920.28 LED192.2@4808.82,4878.7 4798.7,4878.7 4780,4860 4780.15,4859.85 4780.15,4850.04 4780,4849.88 4780,4811.3 C192.1@4799.26,4792.05 4851.3,4740 4900,4740 4900,4755 C193.1@4937.05,4792.05 ; C193.1@4937.05,4792.05 4984.1,4745 5040,4745 5040,4757.2 C194.1@5074.85,4792.05 ; C194.1@5074.85,4792.05 5116.89,4750 5185,4750 5212.64,4777.64 C195.1@5212.64,4792.05 ; C195.1@5212.64,4792.05 5269.69,4735 5325,4735 5325,4766.61 C196.1@5350.44,4792.05 ; C196.1@5350.44,4792.05 5330,4812.48 5330,4855 5353.7,4878.7 LED196.2@5360,4878.7 5360,4920.28 C177.1@5350.44,4929.84 5330,4950.28 5330,5000 5346.5,5016.5 LED177.2@5360,5016.5 5350.44,5026.06 C158.1@5350.44,5067.64 5330,5088.07 5330,5135 5349.29,5154.29 LED158.2@5360,5154.29 5360,5195.87 C139.1@5350.44,5205.43 5330,5225.87 5330,5275 5342.91,5275 LED139.2@5360,5292.09 5360,5333.66 C120.1@5350.44,5343.23 5330,5363.66 5330,5405 5354.88,5429.88 LED120.2@5360,5429.88 5360,5471.46 C101.1@5350.44,5481.02 5330,5501.46 5330,5550 5347.68,5567.68 LED101.2@5360,5567.68 5360,5609.25 C82.1@5350.44,5618.82 5330,5639.26 5330,5685 5335.59,5685 LED82.2@5356.06,5705.47 ; C196.1@5350.44,4792.05 5397.48,4745 5441.18,4745 C197.1@5488.23,4792.05 ; C197.1@5488.23,4792.05 5530.28,4750 5583.98,4750 C198.1@5626.03,4792.05 ; C198.1@5626.03,4792.05 5663.07,4755 5726.77,4755 C199.1@5763.82,4792.05 ; C199.1@5763.82,4792.05 5805.87,4750 5859.57,4750 C200.1@5901.62,4792.05 ; 5880,4855 5880,4813.66 C200.1@5901.62,4792.05 ; C200.1@5901.62,4792.05 5943.66,4750 5997.37,4750 C201.1@6039.41,4792.05 ; C201.1@6039.41,4792.05 6076.46,4755 6140.16,4755 C202.1@6177.21,4792.05 ; C202.1@6177.21,4792.05 6224.26,4745 6267.96,4745 C203.1@6315,4792.05 ; C203.1@6315,4792.05 6290,4817.05 6290,4865 6310.87,4865 LED203.2@6324.57,4878.7 6324.57,4920.28 C184.1@6315,4929.84 6295,4949.85 6295,4995 6316.5,5016.5 LED184.2@6324.57,5016.5 6324.57,5058.07 C165.1@6315,5067.64 6295,5087.64 6295,5135 6314.29,5154.29 LED165.2@6324.57,5154.29 6324.57,5195.87 C146.1@6315,5205.43 6295,5225.44 6295,5275 6312.09,5292.09 LED146.2@6324.57,5292.09 6324.57,5333.66 C127.1@6315,5343.23 6285,5373.23 6285,5415 6299.88,5429.88 LED127.2@6324.57,5429.88 6324.57,5471.46 C108.1@6315,5481.02 6290,5506.03 6290,5550 6306.89,5550 LED108.2@6324.57,5567.68 6324.57,5609.25 C89.1@6315,5618.82 6295,5638.82 6295,5690 6309.09,5690 LED89.2@6324.57,5705.47 6324.57,5747.05 C70.1@6315,5756.61 6290,5781.62 6290,5820 6313.27,5843.27 LED70.2@6324.57,5843.27 6324.57,5884.84 C51.1@6315,5894.41 6295,5914.41 6295,5960 6316.06,5981.06 LED51.2@6324.57,5981.06 6324.57,6022.64 C32.1@6315,6032.2 6290,6057.21 6290,6095 6296.77,6095 LED32.2@6320.63,6118.86 ; C203.1@6315,4792.05 6352.05,4755 6415.75,4755 C204.1@6452.8,4792.05 ; C204.1@6452.8,4792.05 6494.85,4750 6548.55,4750 C205.1@6590.59,4792.05 ; C205.1@6590.59,4792.05 6622.64,4760 6696.34,4760 C206.1@6728.39,4792.05 ; LED170.2@7013.54,5154.29 7204.29,5154.29 7240,5190 7240,5265 7212.91,5292.09 LED152.2@7151.34,5292.09
  Top Layer w20: USB1.12@4338.3,7727.87 4338.3,7752.3 USB1.14@4317.87,7772.73 4317.87,7882.87 4320,7885 4407.55,7885 USB1.14@4422.96,7900.41 4639.38,7683.98 USB1.13@4685.89,7683.98 4685,7683.09 4685,7560 ; v1(4350,6280) 4480,6410 v1(4480,6430) 4483.74,6433.74 C231.1@4483.74,6539.29 C230.1@4483.74,6619.29 4491.73,6627.28 C229.1@4491.73,6704.29 4424.63,6771.39 R16.1@4424.63,6824.29 4375,6873.91 v1(4375,7250) ; v1(4495,7340) 4685,7530 4685,7560 ; USB1.1@4532.85,7567.74 4569.37,7567.74 USB1.13@4580.8,7556.31 4681.31,7556.31 4685,7560
  Bottom Layer w20: v1(4345,6055) 4345,6275 v1(4350,6280) ; v1(4375,7250) 4405,7250 v1(4495,7340) 4500,7335 v1(4500,7135) ; v1(4480,6430) v1(4675,6430)
  other v1: 6830,4065 6500,4240 5530,4450 4740,4500 7175,4575 4545,4700 4420,5040 4325,5420 7450,5555 3545,5710 4120,6335 4240,6435 7460,6440
GPIO0: Boot.4 C226.1 J1.6 R12.1 U1.12 | length 3612.8
  Top Layer w10: v1(6105,6960) 6170,7025 v1(6170,7060) ; C226.1@6971.46,6915 6971.46,6865 7003.59,6832.88 ; Boot.4@7003.59,6769.13 7003.59,6832.88 ; v1(7060,6635) 7060,6776.46 7003.59,6832.88
  Top Layer w20: R12.1@5054.66,7375 v1(5100,7375) ; U1.12@6012.25,6845 v1(6090,6845) 6090,6845.9 U1.12@6012.25,6845.9 U1.12@6012.25,6845
  Bottom Layer w10: v1(6090,6845) 6090,6945 v1(6105,6960) ; v1(6170,7060) 6200.31,7060 6539.78,6720.53 6562.54,6720.53 6614.48,6668.59 6614.48,6645.53 J1.6@6656.79,6603.23 7028.23,6603.23 v1(7060,6635)
  Bottom Layer w20: v1(5100,7375) 4965,7240 4965,6905 4980,6890 6045,6890 v1(6090,6845)
GPIO4: Q1.2 R1.1 U1.13 | length 889.9
  Top Layer w10: U1.13@6012.32,6924.64 6130.36,6924.64 6160,6895 v1(6160,6495) ; v1(6160,6395) 6290.34,6395 R1.1@6300,6385.34 6367.89,6385.34 Q1.2@6380.63,6372.6
  Bottom Layer w10: v1(6160,6395) v1(6160,6495)
LEDIN: LED1.3 Q1.3 R2.1 | length 3723.5
  Top Layer w10: Q1.3@6459.37,6410 6524.66,6410 R2.1@6535,6399.66 6590.34,6399.66 6665,6325 7340,6325 7385,6370 7385,6490 7395,6500 7395,6815 7355,6855 7355,7040 7425,7110 7425,7415 7405,7415 7220,7600 7220,8370.4 7626.26,8776.66 LED1.3@7648.98,8776.66
ROW2IN: LED25.1 LED26.3 | length 83.7
  Top Layer w10: LED25.1@5360,6075.55 5378.5,6075.55 5421.81,6118.86 LED26.3@5425.75,6118.86
ROW3IN: LED50.1 LED51.3 | length 83.7
  Top Layer w10: LED50.1@6186.77,5937.75 6205.27,5937.75 6248.58,5981.06 LED51.3@6252.52,5981.06
ROW4IN: LED75.1 LED76.3 | length 83.7
  Top Layer w10: LED75.1@7013.54,5799.96 7032.04,5799.96 7075.35,5843.27 LED76.3@7079.29,5843.27
ROW5IN: LED100.1 LED101.3 | length 83.7
  Top Layer w10: LED100.1@5222.21,5524.37 5240.7,5524.37 5284.01,5567.68 LED101.3@5287.95,5567.68
ROW6IN: LED125.1 LED126.3 | length 83.7
  Top Layer w10: LED125.1@6048.98,5386.57 6067.48,5386.57 6110.79,5429.88 LED126.3@6114.72,5429.88
ROW7IN: LED150.1 LED151.3 | length 83.7
  Top Layer w10: LED150.1@6875.75,5248.78 6894.25,5248.78 6937.56,5292.09 LED151.3@6941.49,5292.09
ROW8IN: LED175.1 LED176.3 | length 83.7
  Top Layer w10: LED175.1@5084.41,4973.19 5102.91,4973.19 5146.22,5016.5 LED176.3@5150.16,5016.5
ROW9IN: LED200.1 LED201.3 | length 83.7
  Top Layer w10: LED200.1@5911.18,4835.39 5929.68,4835.39 5972.99,4878.7 LED201.3@5976.93,4878.7
RST: R18.1 U1.1 | length 144.8
  Top Layer w10: R18.1@5274.66,7165 5414.6,7165 U1.1@5418.05,7161.55
VCC: C229.2 C230.2 C231.2 C232.2 H1.1 J1.2 L1.2 Q1.1 R1.2 R15.2 R17.2 R18.2 R19.2 U1.8 U2.5 U2.6 | length 5646.8
  Top Layer w10: R15.2@4186.63,7627.46 4187.46,7627.46 v1(4215,7655) ; v1(4295,7595) 4295,7569.1 U2.6@4287.85,7561.96 4290.3,7561.96 U2.5@4302.94,7549.32 ; R19.2@5215.34,7000 R18.2@5215.34,7165 ; R1.2@6300,6444.66 6377.89,6444.66 Q1.1@6380.63,6447.4 6475.52,6542.29 6475.52,6579.87 6500,6604.35 6500,6630 6479.35,6650.65 J1.2@6479.35,6695.5 6520,6736.15 v1(6520,6780)
  Top Layer w20: L1.2@4584.72,7204.29 4584.72,6946.42 C232.2@4596.85,6934.29 4596.85,6831.39 R17.2@4603.95,6824.29 4603.95,6761.39 C229.2@4546.85,6704.29 4546.85,6637.28 C230.2@4564.84,6619.29 C231.2@4564.84,6539.29 4573.79,6530.34 4633.82,6590.37 5215.03,6590.37 ; R19.2@5215.34,7000 5215.34,6590.68 5215.03,6590.37 ; R1.2@6300,6444.66 6297.35,6442.01 5487.99,6442.01 5425,6505 5425,6577.93 5405,6597.93 5397.44,6590.37 5215.03,6590.37
  Bottom Layer w10: H1.1@6360.2,6985.8 6390,6956 6390,6905 6515,6780 v1(6520,6780)
  Bottom Layer w20: v1(4215,7655) 4235,7655 v1(4295,7595) 4320,7595 4450,7465 4755,7465 4900,7320 4900,6780 v1(4710,6590)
